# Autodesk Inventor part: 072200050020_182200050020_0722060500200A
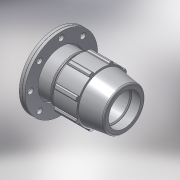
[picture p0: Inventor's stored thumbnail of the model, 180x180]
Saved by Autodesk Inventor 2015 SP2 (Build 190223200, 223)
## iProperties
Created: 2017-02
Part Number: 072200050020_182200050020_0722060500200A
Material: PVC-Piping
Description: PLASSON COMPRESSION FLANGE ADAPTOR 50-2"
Document SubType Name: Modeling
Designer: KIM
Mass: 92.6774 g
Surface Area: 199.44 cm^2
Volume: 66.1981 cm^3
Density: 1.4 g/cm^3
Appearance: Smooth - White
Author: KIM
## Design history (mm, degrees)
derived "07220.ipt"
feature "Solid1::07220.ipt"
tag "TaggingFeature1"
body "Solid1"
other parameters: "d4" = 18.28571, "d5" = 40.96, "d7" = 96, "d9" = 18.28571, "d11" = 3.65714, "d12" = 76.8, "d13" = 120 deg, "d14" = 65, "d15" = 12 deg, "d18" = 2.5, "d19" = 35 deg, "d20" = 17.5 deg, "d21" = 89.28, "d23" = 0, "d25" = 360 deg, "d27" = 1.92, "d42" = 44.8, "d43" = 2.88, "d46" = 1.5, "d53" = 1, "d67" = 4.8, "d68" = 93, "d70" = 128, "d71" = 165, "d73" = 10.66667, "d74" = 90 deg, "d75" = 0.3, "d76" = 165, "d77" = 18, "d78" = 62.5, "d80" = 0, "d82" = 360 deg, "d85" = 81.6, "d86" = 76.8, "d87" = 0.825, "d93" = 6.4, "d95" = 45, "d96" = 0.3, "d99" = 360 deg, "E_" = 96, "H_" = 128, "l_" = 93, "D_" = 165, "Dp_" = 125, "S_" = 18
